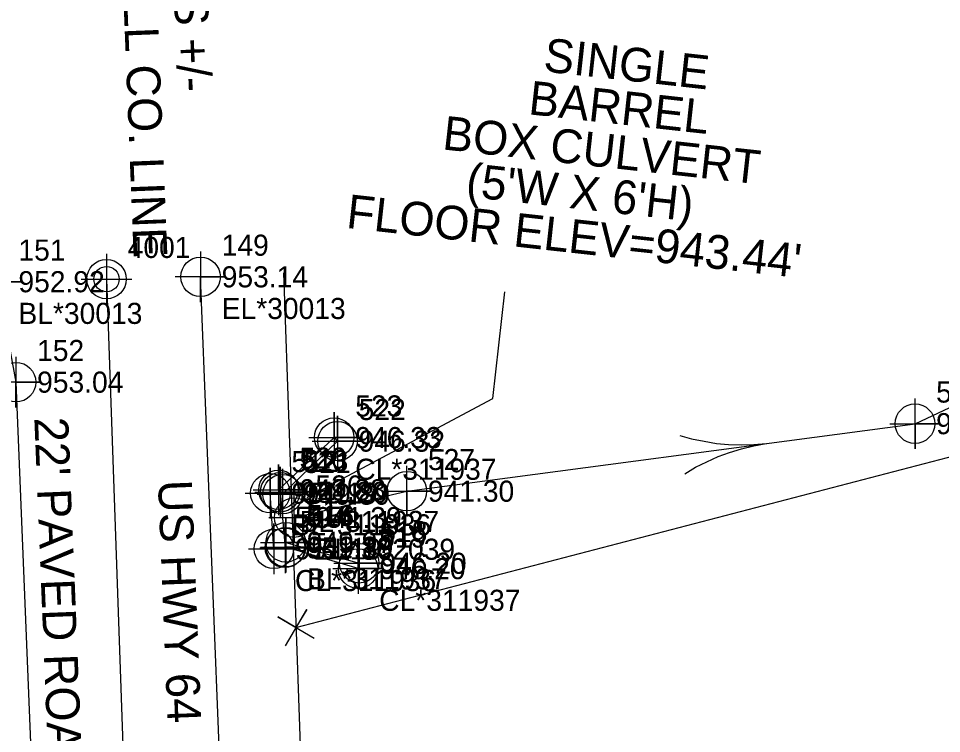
# Model space of a CAD drawing. Extents: x 1150279 to 1151282, y 655434 to 657999.
# Drawn here: x 1150558.1 to 1150667.5, y 657177.3 to 657262 of the extents above; entities that cross this region are included whole.
import ezdxf

# ---------------------------------------------------------------- set-up
doc = ezdxf.new("R2010")
doc.units = 0
for name, color, linetype in [('COGO Default Chain', 7, 'Continuous'), ('Cogo Default Point CELL', 7, 'Continuous'), ('COGO Default Point Number', 7, 'Continuous'), ('Exist Horizontal Alignment', 7, 'Continuous'), ('Exist Horizontal Alignment Station Label', 7, 'Continuous'), ('Exist Hydro Stream Flow Arrow CELL', 7, 'Continuous'), ('Exist Hydro Stream or Body of Water', 7, 'Continuous'), ('Exist Hydro Stream or Body of Water Cogo Comment', 7, 'Continuous'), ('Exist Hydro Stream or Body of Water Cogo Elevation', 7, 'Continuous'), ('Exist Hydro Stream or Body of Water Cogo Number', 7, 'Continuous'), ('Exist Hydro Stream or Body of Water Cogo Point CELL', 7, 'Continuous'), ('Exist Property Corner CELL', 7, 'Continuous'), ('Exist Property Line', 7, 'Continuous'), ('Exist Right of Way Line', 7, 'Continuous'), ('Exist Roads EOP', 7, 'Continuous'), ('Exist Roads EOP Cogo Comment', 7, 'Continuous'), ('Exist Roads EOP Cogo Elevation', 7, 'Continuous'), ('Exist Roads EOP Cogo Number', 7, 'Continuous'), ('Exist Roads EOP Cogo Point CELL', 7, 'Continuous'), ('Exist Roads EOP Text', 7, 'Continuous'), ('Exist Structure Major Bridge WW', 7, 'Continuous'), ('Exist Structure Major Bridge WW Cogo Comment', 7, 'Continuous'), ('Exist Structure Major Bridge WW Cogo Elevation', 7, 'Continuous'), ('Exist Structure Major Bridge WW Cogo Number', 7, 'Continuous'), ('Exist Structure Major Bridge WW Cogo Point CELL', 7, 'Continuous'), ('Exist Structure Major Bridge WW Leader', 7, 'Continuous'), ('Exist Structure Major Bridge WW Text', 7, 'Continuous')]:
    doc.layers.add(name, color=color, linetype=linetype)

msp = doc.modelspace()

# ---------------------------------------------------------------- linework, layer by layer
at = {"layer": 'COGO Default Chain'}
msp.add_line((1150568.54, 657231.15), (1150575.96, 657017.52), dxfattribs=at)
at = {"layer": 'Cogo Default Point CELL'}
for points in [[(1150568.54, 657234.15), (1150568.54, 657231.15)], [(1150565.54, 657231.15), (1150568.54, 657231.15)], [(1150568.54, 657231.15), (1150571.54, 657231.15)], [(1150568.54, 657231.15), (1150568.54, 657228.15)]]:
    msp.add_lwpolyline(points, dxfattribs=at)
msp.add_circle((1150568.54, 657231.15), 2.34, dxfattribs=at)
at = {"layer": 'Exist Horizontal Alignment'}
msp.add_line((1150568.54, 657231.15), (1150575.96, 657017.52), dxfattribs=at)
at = {"layer": 'Exist Horizontal Alignment Station Label'}
msp.add_circle((1150568.54, 657231.15), 1.5, dxfattribs=at)
at = {"layer": 'Exist Hydro Stream Flow Arrow CELL'}
msp.add_line((1150641.7, 657211.02), (1150641.7, 657211.02), dxfattribs=at)
for points in [[(1150636.45, 657212.62), (1150637.85, 657212.21), (1150639.32, 657211.93), (1150640.78, 657211.69), (1150642.22, 657211.56), (1150643.7, 657211.52), (1150645.2, 657211.56), (1150646.66, 657211.67)], [(1150637.05, 657208.09), (1150638.3, 657208.86), (1150639.65, 657209.51), (1150640.99, 657210.13), (1150642.35, 657210.62), (1150643.77, 657211.05), (1150645.22, 657211.41), (1150646.66, 657211.67)]]:
    msp.add_lwpolyline(points, dxfattribs=at)
at = {"layer": 'Exist Hydro Stream or Body of Water'}
msp.add_lwpolyline([(1150590.78, 657202.89), (1150604.11, 657206.02), (1150664.31, 657214.02), (1150690.76, 657226.46), (1150708.05, 657225.68), (1150725.14, 657224.28), (1150732.8, 657228.83), (1150747.96, 657235.28), (1150766.11, 657239.26), (1150781.02, 657229.67)], dxfattribs=at)
at = {"layer": 'Exist Hydro Stream or Body of Water Cogo Point CELL'}
for points in [[(1150661.31, 657214.02), (1150667.31, 657214.02), (1150664.31, 657214.02), (1150664.31, 657211.02), (1150664.31, 657217.02)], [(1150601.11, 657206.02), (1150607.11, 657206.02), (1150604.11, 657206.02), (1150604.11, 657203.02), (1150604.11, 657209.02)], [(1150587.78, 657202.89), (1150593.78, 657202.89), (1150590.78, 657202.89), (1150590.78, 657199.89), (1150590.78, 657205.89)]]:
    msp.add_lwpolyline(points, dxfattribs=at)
for centre in [(1150664.31, 657214.02), (1150604.11, 657206.02), (1150590.78, 657202.89)]:
    msp.add_circle(centre, 2.34, dxfattribs=at)
at = {"layer": 'Exist Property Corner CELL'}
msp.add_line((1150590.98, 657189.86), (1150590.98, 657189.86), dxfattribs=at)
msp.add_lwpolyline([(1150589.72, 657187.7), (1150592.25, 657192.01), (1150590.98, 657189.86), (1150588.83, 657191.12), (1150593.14, 657188.59)], dxfattribs=at)
at = {"layer": 'Exist Property Line'}
msp.add_line((1150590.98, 657189.86), (1150860.41, 657260.23), dxfattribs=at)
at = {"layer": 'Exist Right of Way Line'}
msp.add_line((1150589.52, 657231.88), (1150591.75, 657167.81), dxfattribs=at)
at = {"layer": 'Exist Roads EOP'}
msp.add_line((1150582.24, 657166.76), (1150579.68, 657231.42), dxfattribs=at)
msp.add_lwpolyline([(1150555.6, 657230.84), (1150557.81, 657218.94), (1150559.89, 657167.47), (1150561.73, 657122.25), (1150563.33, 657070.95), (1150564.64, 657020.93), (1150563.6, 657016.73)], dxfattribs=at)
at = {"layer": 'Exist Roads EOP Cogo Point CELL'}
for points in [[(1150555.6, 657233.84), (1150555.6, 657227.84), (1150555.6, 657230.84), (1150558.6, 657230.84), (1150552.6, 657230.84)], [(1150579.68, 657234.42), (1150579.68, 657228.42), (1150579.68, 657231.42), (1150582.68, 657231.42), (1150576.68, 657231.42)], [(1150557.81, 657221.94), (1150557.81, 657215.94), (1150557.81, 657218.94), (1150560.81, 657218.94), (1150554.81, 657218.94)]]:
    msp.add_lwpolyline(points, dxfattribs=at)
for centre in [(1150579.68, 657231.42), (1150557.81, 657218.94)]:
    msp.add_circle(centre, 2.34, dxfattribs=at)
at = {"layer": 'Exist Structure Major Bridge WW'}
for points in [[(1150588.9, 657206.19), (1150589.39, 657205.67), (1150595.91, 657211.95), (1150595.5, 657212.37), (1150588.9, 657206.19)], [(1150587.94, 657205.78), (1150589.1, 657205.89), (1150589.68, 657199.31), (1150588.36, 657199.18), (1150587.94, 657205.78)], [(1150589.79, 657199.38), (1150589.76, 657199.96), (1150598.47, 657197.48), (1150598.34, 657196.84), (1150589.79, 657199.38)]]:
    msp.add_lwpolyline(points, dxfattribs=at)
at = {"layer": 'Exist Structure Major Bridge WW Cogo Point CELL'}
for points in [[(1150592.5, 657212.37), (1150598.5, 657212.37), (1150595.5, 657212.37), (1150595.5, 657215.37), (1150595.5, 657209.37)], [(1150592.91, 657211.95), (1150598.91, 657211.95), (1150595.91, 657211.95), (1150595.91, 657214.95), (1150595.91, 657208.95)], [(1150584.94, 657205.78), (1150590.94, 657205.78), (1150587.94, 657205.78), (1150587.94, 657208.78), (1150587.94, 657202.78)], [(1150585.9, 657206.19), (1150591.9, 657206.19), (1150588.9, 657206.19), (1150588.9, 657209.19), (1150588.9, 657203.19)], [(1150586.1, 657205.89), (1150592.1, 657205.89), (1150589.1, 657205.89), (1150589.1, 657208.89), (1150589.1, 657202.89)], [(1150586.39, 657205.67), (1150592.39, 657205.67), (1150589.39, 657205.67), (1150589.39, 657208.67), (1150589.39, 657202.67)], [(1150586.76, 657199.96), (1150592.76, 657199.96), (1150589.76, 657199.96), (1150589.76, 657202.96), (1150589.76, 657196.96)], [(1150585.36, 657199.18), (1150591.36, 657199.18), (1150588.36, 657199.18), (1150588.36, 657202.18), (1150588.36, 657196.18)], [(1150586.68, 657199.31), (1150592.68, 657199.31), (1150589.68, 657199.31), (1150589.68, 657202.31), (1150589.68, 657196.31)], [(1150586.79, 657199.38), (1150592.79, 657199.38), (1150589.79, 657199.38), (1150589.79, 657202.38), (1150589.79, 657196.38)], [(1150595.34, 657196.84), (1150601.34, 657196.84), (1150598.34, 657196.84), (1150598.34, 657199.84), (1150598.34, 657193.84)], [(1150595.47, 657197.48), (1150601.47, 657197.48), (1150598.47, 657197.48), (1150598.47, 657200.48), (1150598.47, 657194.48)]]:
    msp.add_lwpolyline(points, dxfattribs=at)
for centre in [(1150595.5, 657212.37), (1150595.91, 657211.95), (1150588.9, 657206.19), (1150587.94, 657205.78), (1150589.1, 657205.89), (1150589.39, 657205.67), (1150589.76, 657199.96), (1150588.36, 657199.18), (1150589.68, 657199.31), (1150589.79, 657199.38), (1150598.47, 657197.48), (1150598.34, 657196.84)]:
    msp.add_circle(centre, 2.34, dxfattribs=at)
at = {"layer": 'Exist Structure Major Bridge WW Leader'}
msp.add_lwpolyline([(1150592.31, 657205.26), (1150614.31, 657217.01), (1150615.71, 657229.63)], dxfattribs=at)

# ---------------------------------------------------------------- texts
at = {"layer": 'COGO Default Point Number'}
msp.add_text('4001', height=2.5, dxfattribs=at).set_placement((1150571.04, 657233.65))
at = {"layer": 'Exist Hydro Stream or Body of Water Cogo Comment'}
msp.add_text('BL*362039', height=2.5, dxfattribs=at).set_placement((1150593.28, 657197.89))
at = {"layer": 'Exist Hydro Stream or Body of Water Cogo Elevation'}
for s, p in [('939.69', (1150666.81, 657212.77)), ('941.30', (1150606.61, 657204.77)), ('941.39', (1150593.28, 657201.64))]:
    msp.add_text(s, height=2.5, dxfattribs=at).set_placement(p)
at = {"layer": 'Exist Hydro Stream or Body of Water Cogo Number'}
for s, p in [('531', (1150666.81, 657216.52)), ('527', (1150606.61, 657208.52)), ('526', (1150593.28, 657205.39))]:
    msp.add_text(s, height=2.5, dxfattribs=at).set_placement(p)
at = {"layer": 'Exist Roads EOP Cogo Comment'}
for s, p in [('BL*30013', (1150558.1, 657225.84)), ('EL*30013', (1150582.18, 657226.42))]:
    msp.add_text(s, height=2.5, dxfattribs=at).set_placement(p)
at = {"layer": 'Exist Roads EOP Cogo Elevation'}
for s, p in [('953.14', (1150582.18, 657230.17)), ('952.92', (1150558.1, 657229.59)), ('953.04', (1150560.31, 657217.69))]:
    msp.add_text(s, height=2.5, dxfattribs=at).set_placement(p)
at = {"layer": 'Exist Roads EOP Cogo Number'}
for s, p in [('151', (1150558.1, 657233.34)), ('149', (1150582.18, 657233.92)), ('152', (1150560.31, 657221.44))]:
    msp.add_text(s, height=2.5, dxfattribs=at).set_placement(p)
at = {"layer": 'Exist Roads EOP Text'}
for s, rotation, p in [('TO MCDOWELL CO. LINE', 272.2625, (1150569.22, 657297.77)), ('1.40 MILES +/-', 272.2625, (1150575.57, 657289.05)), ("22' PAVED ROADWAY", 272.3134, (1150559.98, 657214.72)), ('US HWY 64', 272.2625, (1150574.63, 657207.28))]:
    msp.add_text(s, height=4, rotation=rotation, dxfattribs=at).set_placement(p)
at = {"layer": 'Exist Structure Major Bridge WW Cogo Comment'}
for s, p in [('CL*311937', (1150598, 657207.37)), ('BL*311936', (1150590.44, 657200.78)), ('BL*311937', (1150591.4, 657201.19)), ('CL*311936', (1150590.86, 657194.18)), ('BL*311937', (1150592.29, 657194.38)), ('CL*311937', (1150600.84, 657191.84))]:
    msp.add_text(s, height=2.5, dxfattribs=at).set_placement(p)
at = {"layer": 'Exist Structure Major Bridge WW Cogo Elevation'}
for s, p in [('946.33', (1150598, 657211.12)), ('946.32', (1150598.41, 657210.7)), ('949.88', (1150591.4, 657204.94)), ('951.19', (1150590.44, 657204.53)), ('951.20', (1150591.6, 657204.64)), ('949.89', (1150591.89, 657204.42)), ('949.97', (1150592.26, 657198.71)), ('951.19', (1150590.86, 657197.93)), ('951.18', (1150592.18, 657198.06)), ('949.89', (1150592.29, 657198.13)), ('946.20', (1150600.97, 657196.23)), ('946.20', (1150600.84, 657195.59))]:
    msp.add_text(s, height=2.5, dxfattribs=at).set_placement(p)
at = {"layer": 'Exist Structure Major Bridge WW Cogo Number'}
for s, p in [('523', (1150598, 657214.87)), ('522', (1150598.41, 657214.45)), ('512', (1150590.44, 657208.28)), ('520', (1150591.4, 657208.69)), ('513', (1150591.6, 657208.39)), ('521', (1150591.89, 657208.17)), ('515', (1150590.86, 657201.68)), ('514', (1150592.18, 657201.81)), ('517', (1150592.26, 657202.46)), ('516', (1150592.29, 657201.88)), ('519', (1150600.84, 657199.34)), ('518', (1150600.97, 657199.98))]:
    msp.add_text(s, height=2.5, dxfattribs=at).set_placement(p)
at = {"layer": 'Exist Structure Major Bridge WW Text'}
for s, p in [('SINGLE', (1150620.2, 657255.77)), ('BARREL', (1150618.42, 657250.69)), ('BOX CULVERT', (1150608.23, 657246.53)), ("(5'W X 6'H)", (1150611, 657240.94)), ("FLOOR ELEV=943.44'", (1150596.84, 657237.23))]:
    msp.add_text(s, height=4, rotation=353.6867, dxfattribs=at).set_placement(p)

doc.saveas('drawing.dxf')
